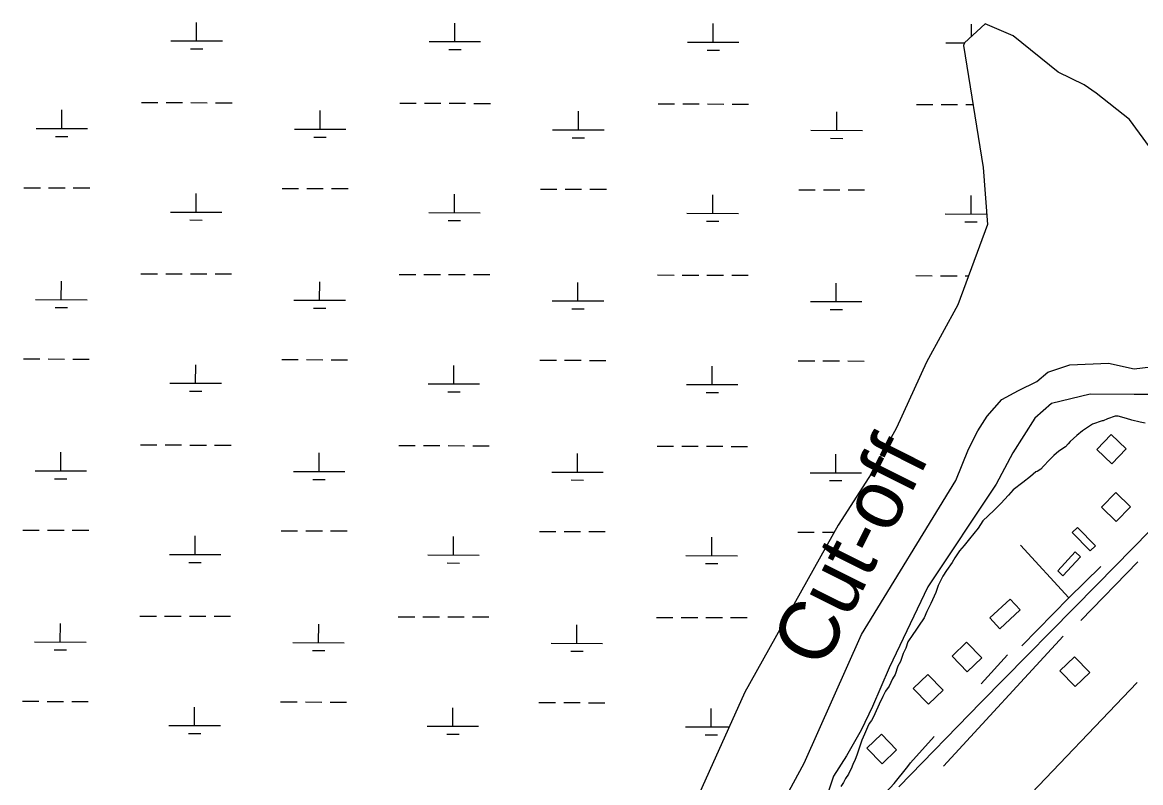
# Model space of a CAD drawing. Extents: x 3172297 to 3210190, y 958463 to 983887.
# Drawn here: x 3177174 to 3179346, y 979396 to 980873 of the extents above; entities that cross this region are included whole.
import ezdxf

# ---------------------------------------------------------------- set-up
doc = ezdxf.new("R2010")
doc.units = 0
for name, color, linetype in [('V-BLDG-OTLN', 7, 'Continuous'), ('V-RIVR-IDEN', 7, 'Continuous'), ('V-ROAD-CNTR', 7, 'Continuous'), ('V-SITE-VEGE', 7, 'Continuous'), ('V-TOPO-SHOR', 7, 'Continuous'), ('V-WETL-SWMP', 7, 'Continuous')]:
    doc.layers.add(name, color=color, linetype=linetype)

msp = doc.modelspace()

# ---------------------------------------------------------------- linework, layer by layer
at = {"layer": 'V-BLDG-OTLN'}
for points in [[(3179290.1, 980015.2), (3179318, 980043.9), (3179289.3, 980071.8), (3179261.4, 980043.1)], [(3179298.6, 979902.8), (3179326.5, 979931.5), (3179297.9, 979959.4), (3179270, 979930.7)], [(3179223.3, 979891.5), (3179258.4, 979855.9), (3179248.5, 979846.1), (3179213.4, 979881.7)], [(3179185.1, 979807.1), (3179219.1, 979843.9), (3179229.3, 979834.3), (3179195.4, 979797.6)], [(3179053.3, 979716.1), (3179092.9, 979752.3), (3179112.3, 979731.2), (3179072.6, 979694.9)], [(3178979.9, 979641.4), (3179008.2, 979668.7), (3179037.7, 979638.2), (3179009.4, 979610.9)], [(3179189.5, 979612.9), (3179217.8, 979640.2), (3179247.3, 979609.6), (3179219, 979582.3)], [(3178904.6, 979578.9), (3178932.9, 979606.2), (3178962.4, 979575.7), (3178934.1, 979548.4)], [(3178814.4, 979462.7), (3178842.6, 979490), (3178872.1, 979459.5), (3178843.9, 979432.2)]]:
    msp.add_lwpolyline(points, close=True, dxfattribs=at)
at = {"layer": 'V-ROAD-CNTR'}
msp.add_lwpolyline([(3179398.9, 979920.6), (3179261, 979779.9), (3179036.6, 979551.9), (3178876.2, 979387.8)], dxfattribs=at)
at = {"layer": 'V-SITE-VEGE'}
for p, q in [((3179271.5, 980098.6), (3179252.7, 980092.4)), ((3179273.8, 980098.5), (3179271.5, 980098.6)), ((3179281.7, 980102.4), (3179273.8, 980098.5)), ((3179296.5, 980107.8), (3179281.7, 980102.4)), ((3179302.8, 980107.7), (3179296.5, 980107.8)), ((3179319.1, 980102.9), (3179302.8, 980107.7)), ((3179329.3, 980099.7), (3179319.1, 980102.9)), ((3179345.6, 980095.7), (3179329.3, 980099.7)), ((3179233.1, 980079.3), (3179222.1, 980070)), ((3179252.7, 980092.4), (3179233.1, 980079.3)), ((3179355, 980094.1), (3179345.6, 980095.7)), ((3179209.5, 980058.4), (3179205.6, 980053.7)), ((3179222.1, 980070), (3179209.5, 980058.4)), ((3179187.6, 980039.8), (3179177.4, 980031.3)), ((3179200.1, 980048.3), (3179187.6, 980039.8)), ((3179205.6, 980053.7), (3179200.1, 980048.3)), ((3179168.7, 980021.9), (3179157.7, 980010.3)), ((3179177.4, 980031.3), (3179168.7, 980021.9)), ((3179132.6, 979990.2), (3179117.7, 979978.6)), ((3179142.8, 979999.5), (3179132.6, 979990.2)), ((3179145.1, 980000.2), (3179142.8, 979999.5)), ((3179152.2, 980004.9), (3179145.1, 980000.2)), ((3179157.7, 980010.3), (3179152.2, 980004.9)), ((3179117.7, 979978.6), (3179098.8, 979964.6)), ((3179089.4, 979954.5), (3179074.5, 979938.2)), ((3179098.8, 979964.6), (3179089.4, 979954.5)), ((3179074.5, 979938.2), (3179061.1, 979924.3)), ((3179039.9, 979904.1), (3179030.4, 979890.1)), ((3179061.1, 979924.3), (3179039.9, 979904.1)), ((3179030.4, 979890.1), (3179013.9, 979869.2)), ((3179013.9, 979869.2), (3179003.7, 979856.7)), ((3178994.2, 979845.9), (3178985.5, 979832.7)), ((3179003.7, 979856.7), (3178994.2, 979845.9)), ((3178980, 979823.3), (3178969, 979807.8)), ((3178985.5, 979832.7), (3178980, 979823.3)), ((3178961.9, 979796.9), (3178953.2, 979779)), ((3178969, 979807.8), (3178961.9, 979796.9)), ((3178953.2, 979779), (3178948.4, 979765)), ((3178948.4, 979765), (3178938.9, 979744)), ((3178938.9, 979744), (3178931, 979728.4)), ((3178925.4, 979715.9), (3178914.4, 979699.6)), ((3178931, 979728.4), (3178925.4, 979715.9)), ((3178909.7, 979691.8), (3178903.4, 979683.3)), ((3178914.4, 979699.6), (3178909.7, 979691.8)), ((3178893.9, 979669.3), (3178889.9, 979656.8)), ((3178903.4, 979683.3), (3178893.9, 979669.3)), ((3178885.2, 979646.7), (3178879.6, 979631.1)), ((3178889.9, 979656.8), (3178885.2, 979646.7)), ((3178874.8, 979621.8), (3178869.3, 979606.2)), ((3178879.6, 979631.1), (3178874.8, 979621.8)), ((3178869.3, 979606.2), (3178864.5, 979597.7)), ((3178857.4, 979582.9), (3178850.3, 979573.6)), ((3178864.5, 979597.7), (3178857.4, 979582.9)), ((3178841.6, 979555.7), (3178826.6, 979522.2)), ((3178844.8, 979561.1), (3178841.6, 979555.7)), ((3178845.6, 979563.4), (3178844.8, 979561.1)), ((3178850.3, 979573.6), (3178845.6, 979563.4)), ((3178823.4, 979516.7), (3178818.7, 979510.5)), ((3178826.6, 979522.2), (3178823.4, 979516.7)), ((3178809.9, 979490.3), (3178804.4, 979478.6)), ((3178815.5, 979503.5), (3178809.9, 979490.3)), ((3178818.7, 979510.5), (3178815.5, 979503.5)), ((3178804.4, 979478.6), (3178798.8, 979460.7)), ((3178795.6, 979451.3), (3178790.9, 979438.9)), ((3178798.8, 979460.7), (3178795.6, 979451.3)), ((3178785.3, 979425.6), (3178779, 979412.4)), ((3178787.7, 979432.7), (3178785.3, 979425.6)), ((3178790.9, 979438.9), (3178787.7, 979432.7)), ((3178772.7, 979403.9), (3178768.7, 979396.1)), ((3178779, 979412.4), (3178772.7, 979403.9)), ((3178768.7, 979396.1), (3178764, 979388.3))]:
    msp.add_line(p, q, dxfattribs=at)
at = {"layer": 'V-TOPO-SHOR'}
for p, q in [((3179341, 979824.9), (3179230, 979710.9)), ((3179206.5, 979755.1), (3179269.1, 979815.7)), ((3179196, 979680.6), (3178963.3, 979427.6)), ((3179036.4, 979587.7), (3179087.4, 979643.8)), ((3179054.9, 979292.6), (3179339.5, 979590.1))]:
    msp.add_line(p, q, dxfattribs=at)
for points in [[(3178570.8, 979209), (3178692.8, 979433.7), (3178804.1, 979683.4), (3178987, 979982.9), (3179012.1, 980043.5), (3179030, 980079.2), (3179048, 980107.7), (3179076.6, 980139.8), (3179108.8, 980157.6), (3179144.6, 980175.3), (3179166, 980193.1), (3179208.9, 980207.3), (3179283.9, 980210.7), (3179333.9, 980199.9), (3179366, 980203.4)], [(3179390.9, 980149.7), (3179333.8, 980149.9), (3179248.1, 980150.1), (3179173, 980132.4), (3179140.8, 980103.9), (3179097.8, 980036.2), (3179065.5, 979975.6), (3178932.9, 979775.9), (3178857.5, 979619), (3178825.2, 979544), (3178803.6, 979497.7), (3178774.9, 979447.8), (3178749.8, 979408.5), (3178713.9, 979301.5)], [(3179115.2, 979661.6), (3179206.5, 979755.1), (3179113, 979857.1)], [(3178330.8, 978727.1), (3178346, 978734.2), (3178360.3, 978749.3), (3178381.8, 978766.2), (3178406.8, 978792.9), (3178472.2, 978860.6), (3178530.4, 978931), (3178568.9, 978989.8), (3178717.7, 979208.2), (3178744.5, 979251.9), (3178783, 979294.6), (3178818, 979341), (3178867.2, 979394.4), (3178894.1, 979427.4), (3178899.4, 979434.5), (3178945.1, 979485.3)]]:
    msp.add_lwpolyline(points, dxfattribs=at)
at = {"layer": 'V-WETL-SWMP'}
for p, q in [((3177512.1, 980836.6), (3177512.2, 980872.6)), ((3178014, 980835.3), (3178014.1, 980871.3)), ((3178515.8, 980834.1), (3178516, 980870.1)), ((3179043.9, 980870), (3179003.8, 980832.8)), ((3179017.7, 980845.7), (3179017.8, 980868.8)), ((3179098.4, 980846.3), (3179043.9, 980870)), ((3179186.1, 980775.6), (3179098.4, 980846.3)), ((3177462.1, 980836.7), (3177562.1, 980836.5)), ((3177500.1, 980821.2), (3177524.1, 980821.1)), ((3177964, 980835.5), (3178064, 980835.2)), ((3178001.9, 980819.9), (3178025.9, 980819.9)), ((3178465.9, 980834.2), (3178565.8, 980834)), ((3178503.8, 980818.7), (3178527.8, 980818.6)), ((3178967.7, 980833), (3179003.9, 980832.9)), ((3179003.8, 980832.8), (3179002.2, 980827.4)), ((3179002.2, 980827.4), (3179040.4, 980590.8)), ((3179236.7, 980751.1), (3179186.1, 980775.6)), ((3179260, 980735.3), (3179236.7, 980751.1)), ((3179324.4, 980684.2), (3179260, 980735.3)), ((3177404.9, 980716.8), (3177436.9, 980716.8)), ((3177452.9, 980716.7), (3177484.9, 980716.6)), ((3177500.9, 980716.6), (3177532.9, 980716.5)), ((3177548.9, 980716.5), (3177580.9, 980716.4)), ((3177906.8, 980715.6), (3177938.8, 980715.5)), ((3177954.8, 980715.5), (3177986.8, 980715.4)), ((3178002.8, 980715.4), (3178034.8, 980715.3)), ((3178050.8, 980715.2), (3178082.8, 980715.2)), ((3178408.7, 980714.4), (3178440.7, 980714.3)), ((3178456.7, 980714.2), (3178488.7, 980714.2)), ((3178504.7, 980714.1), (3178536.6, 980714)), ((3178552.6, 980714), (3178584.6, 980713.9)), ((3178910.5, 980713.1), (3178942.5, 980713)), ((3178958.5, 980713), (3178990.5, 980712.9)), ((3179006.5, 980712.9), (3179020.7, 980712.8)), ((3177250.2, 980666.5), (3177250.3, 980702.5)), ((3177752.1, 980665.3), (3177752.2, 980701.2)), ((3178253.9, 980664), (3178254, 980700)), ((3178755.8, 980662.8), (3178755.9, 980698.8)), ((3177200.2, 980666.6), (3177300.2, 980666.4)), ((3177702.1, 980665.4), (3177802.1, 980665.1)), ((3178203.9, 980664.1), (3178303.9, 980663.9)), ((3179400.9, 980579.3), (3179324.4, 980684.2)), ((3177238.2, 980651.1), (3177262.2, 980651.1)), ((3177740, 980649.9), (3177764, 980649.8)), ((3178241.9, 980648.6), (3178265.9, 980648.6)), ((3178705.8, 980662.9), (3178805.8, 980662.7)), ((3178743.8, 980647.4), (3178767.7, 980647.3)), ((3179040.4, 980590.8), (3179049, 980480.1)), ((3177176.5, 980551.3), (3177208.5, 980551.2)), ((3177224.5, 980551.2), (3177256.5, 980551.1)), ((3177272.5, 980551.1), (3177304.5, 980551)), ((3177511.2, 980504.1), (3177511.3, 980540.1)), ((3177678.3, 980550.1), (3177710.3, 980550)), ((3177726.3, 980550), (3177758.3, 980549.9)), ((3177774.3, 980549.8), (3177806.3, 980549.8)), ((3178013, 980502.8), (3178013.1, 980538.8)), ((3178180.2, 980548.8), (3178212.2, 980548.8)), ((3178228.2, 980548.7), (3178260.2, 980548.6)), ((3178276.2, 980548.6), (3178308.2, 980548.5)), ((3178514.9, 980501.6), (3178515, 980537.6)), ((3178682.1, 980547.6), (3178714.1, 980547.5)), ((3178730.1, 980547.5), (3178762, 980547.4)), ((3178778, 980547.4), (3178810, 980547.3)), ((3179016.7, 980500.4), (3179016.8, 980536.3)), ((3177461.2, 980504.2), (3177561.1, 980504)), ((3177963, 980503), (3178063, 980502.7)), ((3178464.9, 980501.7), (3178564.9, 980501.5)), ((3178966.7, 980500.5), (3179047.4, 980500.3)), ((3177499.1, 980488.7), (3177523.1, 980488.6)), ((3178001, 980487.5), (3178025, 980487.4)), ((3178502.8, 980486.2), (3178526.8, 980486.2)), ((3179049, 980480.1), (3178990.9, 980323.7)), ((3179004.7, 980485), (3179028.7, 980484.9)), ((3177404, 980384.4), (3177436, 980384.3)), ((3177452, 980384.2), (3177484, 980384.2)), ((3177500, 980384.1), (3177532, 980384)), ((3177548, 980384), (3177579.9, 980383.9)), ((3177905.8, 980383.1), (3177937.8, 980383)), ((3177953.8, 980383), (3177985.8, 980382.9)), ((3178001.8, 980382.9), (3178033.8, 980382.8)), ((3178049.8, 980382.8), (3178081.8, 980382.7)), ((3178407.7, 980381.9), (3178439.7, 980381.8)), ((3178455.7, 980381.7), (3178487.7, 980381.7)), ((3178503.7, 980381.6), (3178535.7, 980381.6)), ((3178551.7, 980381.5), (3178583.7, 980381.4)), ((3177249.2, 980334), (3177249.3, 980370)), ((3177751.1, 980332.8), (3177751.2, 980368.8)), ((3178253, 980331.5), (3178253.1, 980367.5)), ((3178754.8, 980330.3), (3178754.9, 980366.3)), ((3178909.5, 980380.6), (3178941.5, 980380.5)), ((3178957.5, 980380.5), (3178989.5, 980380.4)), ((3179005.5, 980380.4), (3179011.9, 980380.4)), ((3177199.2, 980334.1), (3177299.2, 980333.9)), ((3177237.2, 980318.6), (3177261.2, 980318.6)), ((3177701.1, 980332.9), (3177801.1, 980332.7)), ((3177739.1, 980317.4), (3177763.1, 980317.3)), ((3178203, 980331.7), (3178303, 980331.4)), ((3178240.9, 980316.1), (3178264.9, 980316.1)), ((3178704.8, 980330.4), (3178804.8, 980330.2)), ((3178990.9, 980323.7), (3178930, 980212.5)), ((3178742.8, 980314.9), (3178766.8, 980314.8)), ((3177175.5, 980218.8), (3177207.5, 980218.8)), ((3177223.5, 980218.7), (3177255.5, 980218.6)), ((3177271.5, 980218.6), (3177303.5, 980218.5)), ((3177510.2, 980171.6), (3177510.3, 980207.6)), ((3177677.4, 980217.6), (3177709.4, 980217.5)), ((3177725.4, 980217.5), (3177757.4, 980217.4)), ((3177773.4, 980217.4), (3177805.4, 980217.3)), ((3178179.2, 980216.4), (3178211.2, 980216.3)), ((3178227.2, 980216.2), (3178259.2, 980216.2)), ((3178275.2, 980216.1), (3178307.2, 980216)), ((3178681.1, 980215.1), (3178713.1, 980215)), ((3178729.1, 980215), (3178761.1, 980214.9)), ((3178777.1, 980214.9), (3178809.1, 980214.8)), ((3178930, 980212.5), (3178872.1, 980085)), ((3178012, 980170.4), (3178012.1, 980206.3)), ((3178513.9, 980169.1), (3178514, 980205.1)), ((3177460.2, 980171.7), (3177560.2, 980171.5)), ((3177962, 980170.5), (3178062, 980170.2)), ((3178463.9, 980169.2), (3178563.9, 980169)), ((3177498.1, 980156.2), (3177522.1, 980156.2)), ((3178000, 980155), (3178024, 980154.9)), ((3178501.9, 980153.7), (3178525.9, 980153.7)), ((3178872.1, 980085), (3178823.9, 979997.9)), ((3177248.3, 980001.5), (3177248.4, 980037.5)), ((3177403, 980051.9), (3177435, 980051.8)), ((3177451, 980051.7), (3177483, 980051.7)), ((3177499, 980051.6), (3177531, 980051.5)), ((3177547, 980051.5), (3177579, 980051.4)), ((3177750.1, 980000.3), (3177750.2, 980036.3)), ((3177904.9, 980050.6), (3177936.9, 980050.5)), ((3177952.8, 980050.5), (3177984.8, 980050.4)), ((3178000.8, 980050.4), (3178032.8, 980050.3)), ((3178048.8, 980050.3), (3178080.8, 980050.2)), ((3178252, 979999.1), (3178252.1, 980035)), ((3178406.7, 980049.4), (3178438.7, 980049.3)), ((3178454.7, 980049.3), (3178486.7, 980049.2)), ((3178502.7, 980049.1), (3178534.7, 980049.1)), ((3178550.7, 980049), (3178582.7, 980048.9)), ((3178753.8, 979997.8), (3178754, 980033.8)), ((3177198.3, 980001.7), (3177298.3, 980001.4)), ((3177700.1, 980000.4), (3177800.1, 980000.2)), ((3178202, 979999.2), (3178302, 979998.9)), ((3178703.9, 979997.9), (3178803.8, 979997.7)), ((3178823.9, 979997.9), (3178758.4, 979896.2)), ((3177236.2, 979986.1), (3177260.2, 979986.1)), ((3177738.1, 979984.9), (3177762.1, 979984.8)), ((3178239.9, 979983.7), (3178263.9, 979983.6)), ((3178741.8, 979982.4), (3178765.8, 979982.4)), ((3177174.5, 979886.3), (3177206.5, 979886.3)), ((3177222.5, 979886.2), (3177254.5, 979886.1)), ((3177270.5, 979886.1), (3177302.5, 979886)), ((3177676.4, 979885.1), (3177708.4, 979885)), ((3177724.4, 979885), (3177756.4, 979884.9)), ((3177772.4, 979884.9), (3177804.4, 979884.8)), ((3178178.2, 979883.9), (3178210.2, 979883.8)), ((3178226.2, 979883.7), (3178258.2, 979883.7)), ((3178274.2, 979883.6), (3178306.2, 979883.5)), ((3178758.4, 979896.2), (3178577.3, 979571.3)), ((3178680.1, 979882.6), (3178712.1, 979882.5)), ((3178728.1, 979882.5), (3178750.7, 979882.5)), ((3177509.2, 979839.1), (3177509.3, 979875.1)), ((3178011.1, 979837.9), (3178011.2, 979873.9)), ((3178512.9, 979836.6), (3178513, 979872.6)), ((3177459.2, 979839.2), (3177559.2, 979839)), ((3177961.1, 979838), (3178061.1, 979837.8)), ((3177497.2, 979823.7), (3177521.2, 979823.7)), ((3177999, 979822.5), (3178023, 979822.4)), ((3178462.9, 979836.8), (3178562.9, 979836.5)), ((3178500.9, 979821.2), (3178524.9, 979821.2)), ((3177402, 979719.4), (3177434, 979719.3)), ((3177450, 979719.3), (3177482, 979719.2)), ((3177498, 979719.1), (3177530, 979719.1)), ((3177546, 979719), (3177578, 979718.9)), ((3177903.9, 979718.1), (3177935.9, 979718.1)), ((3177951.9, 979718), (3177983.9, 979717.9)), ((3177999.9, 979717.9), (3178031.9, 979717.8)), ((3178047.9, 979717.8), (3178079.9, 979717.7)), ((3178405.7, 979716.9), (3178437.7, 979716.8)), ((3178453.7, 979716.8), (3178485.7, 979716.7)), ((3178501.7, 979716.7), (3178533.7, 979716.6)), ((3178549.7, 979716.5), (3178581.7, 979716.5)), ((3177247.3, 979669), (3177247.4, 979705)), ((3177749.2, 979667.8), (3177749.3, 979703.8)), ((3178251, 979666.6), (3178251.1, 979702.5)), ((3177197.3, 979669.2), (3177297.3, 979668.9)), ((3177699.2, 979667.9), (3177799.1, 979667.7)), ((3178201, 979666.7), (3178301, 979666.4)), ((3177235.3, 979653.7), (3177259.2, 979653.6)), ((3177737.1, 979652.4), (3177761.1, 979652.4)), ((3178239, 979651.2), (3178263, 979651.1)), ((3178577.3, 979571.3), (3178448.8, 979286.7)), ((3177173.6, 979553.9), (3177205.6, 979553.8)), ((3177221.6, 979553.7), (3177253.5, 979553.7)), ((3177269.5, 979553.6), (3177301.5, 979553.5)), ((3177508.2, 979506.6), (3177508.3, 979542.6)), ((3177675.4, 979552.6), (3177707.4, 979552.5)), ((3177723.4, 979552.5), (3177755.4, 979552.4)), ((3177771.4, 979552.4), (3177803.4, 979552.3)), ((3178010.1, 979505.4), (3178010.2, 979541.4)), ((3178177.3, 979551.4), (3178209.3, 979551.3)), ((3178225.3, 979551.3), (3178257.3, 979551.2)), ((3178273.3, 979551.1), (3178305.3, 979551.1)), ((3178512, 979504.1), (3178512.1, 979540.1)), ((3177458.2, 979506.8), (3177558.2, 979506.5)), ((3177496.2, 979491.2), (3177520.2, 979491.2)), ((3177960.1, 979505.5), (3178060.1, 979505.3)), ((3177998, 979490), (3178022, 979489.9)), ((3178462, 979504.3), (3178547, 979504.1)), ((3178499.9, 979488.8), (3178523.9, 979488.7))]:
    msp.add_line(p, q, dxfattribs=at)

# ---------------------------------------------------------------- texts
at = {"layer": 'V-RIVR-IDEN'}
msp.add_text('Cut-off', height=116, rotation=63.3835, dxfattribs=at).set_placement((3178728.6, 979612.7))

doc.saveas('drawing.dxf')
